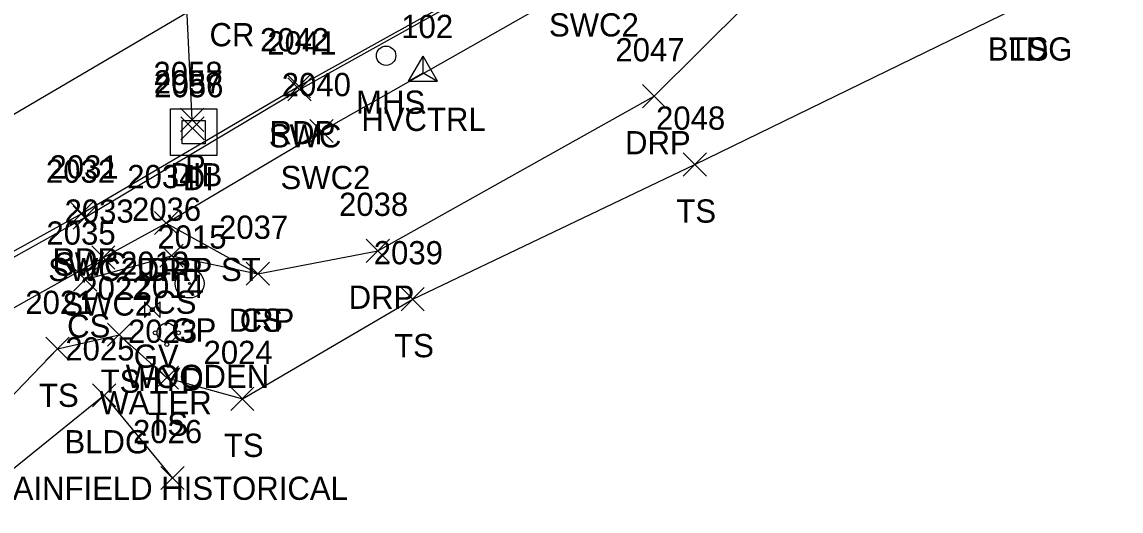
# Model space of a CAD drawing. Extents: x 1657482 to 1661439, y 647981 to 649041.
# Drawn here: x 1660079.4 to 1660173.9, y 648150.8 to 648192.9 of the extents above; entities that cross this region are included whole.
import ezdxf

# ---------------------------------------------------------------- set-up
doc = ezdxf.new("R2010")
doc.units = 0
for name, color, linetype in [('C_A', 7, 'Continuous'), ('C_I', 7, 'Continuous'), ('CPSM', 7, 'Continuous'), ('D_A', 7, 'Continuous'), ('D_I', 7, 'Continuous'), ('D_TIC', 7, 'Continuous'), ('DCP', 7, 'Continuous'), ('DS', 7, 'Continuous'), ('L_A', 7, 'Continuous'), ('L_C', 7, 'Continuous'), ('L_I', 7, 'Continuous'), ('L_TIC', 7, 'Continuous'), ('LBC', 7, 'Continuous'), ('LELB', 7, 'Continuous'), ('P_A', 7, 'Continuous'), ('P_I', 7, 'Continuous'), ('P_TIC', 7, 'Continuous'), ('PET', 7, 'Continuous'), ('PRC', 7, 'Continuous'), ('R_A', 7, 'Continuous'), ('R_C', 7, 'Continuous'), ('R_I', 7, 'Continuous'), ('R_TIC', 7, 'Continuous'), ('RDP', 7, 'Continuous'), ('RGP', 7, 'Continuous'), ('RSW', 7, 'Continuous'), ('U_A', 7, 'Continuous'), ('U_C', 7, 'Continuous'), ('U_I', 7, 'Continuous'), ('USMH', 7, 'Continuous'), ('UWFH', 7, 'Continuous'), ('UWV', 7, 'Continuous')]:
    doc.layers.add(name, color=color, linetype=linetype)

msp = doc.modelspace()

# ---------------------------------------------------------------- linework, layer by layer
at = {"layer": 'CPSM'}
for p, q in [((1660112.623, 648187.758), (1660113.873, 648189.923)), ((1660115.123, 648187.758), (1660113.873, 648189.923)), ((1660113.873, 648188.479), (1660113.873, 648189.923)), ((1660112.623, 648187.758), (1660113.873, 648188.479)), ((1660113.873, 648188.479), (1660113.873, 648188.479)), ((1660113.873, 648188.479), (1660115.123, 648187.758)), ((1660112.623, 648187.758), (1660115.123, 648187.758))]:
    msp.add_line(p, q, dxfattribs=at)
at = {"layer": 'D_TIC'}
for points in [[(1660093.024, 648183.435), (1660095.024, 648185.435)], [(1660095.024, 648183.435), (1660093.024, 648185.435)], [(1660093.048, 648182.707), (1660095.048, 648184.707)], [(1660095.048, 648182.707), (1660093.048, 648184.707)]]:
    msp.add_lwpolyline(points, dxfattribs=at)
at = {"layer": 'DCP'}
msp.add_lwpolyline([(1660094.024, 648184.435), (1660093.004, 648205.604)], dxfattribs=at)
at = {"layer": 'DS'}
for p, q in [((1660092.146, 648185.375), (1660096.146, 648185.375)), ((1660092.146, 648181.375), (1660092.146, 648185.375)), ((1660096.146, 648185.375), (1660096.146, 648181.375)), ((1660093.146, 648182.375), (1660093.146, 648184.375)), ((1660093.146, 648184.375), (1660095.146, 648184.375)), ((1660095.146, 648184.375), (1660095.146, 648182.375)), ((1660094.151, 648183.377), (1660094.151, 648183.377)), ((1660094.151, 648183.377), (1660094.151, 648183.377)), ((1660095.146, 648182.375), (1660093.146, 648182.375)), ((1660096.146, 648181.375), (1660092.146, 648181.375))]:
    msp.add_line(p, q, dxfattribs=at)
at = {"layer": 'L_TIC'}
for points in [[(1660136.252, 648179.586), (1660138.252, 648181.586)], [(1660138.252, 648179.586), (1660136.252, 648181.586)], [(1660091.233, 648171.74), (1660093.233, 648173.74)], [(1660093.233, 648171.74), (1660091.233, 648173.74)], [(1660098.665, 648170.191), (1660100.665, 648172.191)], [(1660100.665, 648170.191), (1660098.665, 648172.191)], [(1660083.823, 648169.69), (1660085.823, 648171.69)], [(1660085.823, 648169.69), (1660083.823, 648171.69)], [(1660111.982, 648167.997), (1660113.982, 648169.997)], [(1660113.982, 648167.997), (1660111.982, 648169.997)], [(1660086.736, 648164.939), (1660088.736, 648166.939)], [(1660088.736, 648164.939), (1660086.736, 648166.939)], [(1660081.438, 648163.723), (1660083.438, 648165.723)], [(1660083.438, 648163.723), (1660081.438, 648165.723)], [(1660090.837, 648161.237), (1660092.837, 648163.237)], [(1660092.837, 648161.237), (1660090.837, 648163.237)], [(1660085.444, 648159.719), (1660087.444, 648161.719)], [(1660087.444, 648159.719), (1660085.444, 648161.719)], [(1660097.334, 648159.413), (1660099.334, 648161.413)], [(1660099.334, 648159.413), (1660097.334, 648161.413)], [(1660091.319, 648152.599), (1660093.319, 648154.599)], [(1660093.319, 648152.599), (1660091.319, 648154.599)]]:
    msp.add_lwpolyline(points, dxfattribs=at)
at = {"layer": 'LBC'}
msp.add_lwpolyline([(1660067.676, 648144.921), (1660075.653, 648152.015), (1660086.444, 648160.719), (1660092.319, 648153.599)], dxfattribs=at)
at = {"layer": 'LELB'}
for points in [[(1660062.987, 648150.882), (1660075.31, 648157.317), (1660082.438, 648164.723), (1660087.736, 648165.939), (1660091.837, 648162.237), (1660098.334, 648160.413), (1660112.982, 648168.997), (1660137.252, 648180.586), (1660165.85, 648194.537)], [(1660084.823, 648170.69), (1660092.233, 648172.74), (1660099.665, 648171.191)]]:
    msp.add_lwpolyline(points, dxfattribs=at)
at = {"layer": 'P_TIC'}
for points in [[(1660102.189, 648186.334), (1660104.189, 648188.334)], [(1660104.189, 648186.334), (1660102.189, 648188.334)], [(1660083.515, 648175.384), (1660085.515, 648177.384)], [(1660085.515, 648175.384), (1660083.515, 648177.384)]]:
    msp.add_lwpolyline(points, dxfattribs=at)
at = {"layer": 'PET'}
msp.add_lwpolyline([(1660002.916, 648130.398), (1660023.122, 648141.511), (1660054.019, 648158.569), (1660066.127, 648166.199), (1660084.515, 648176.384), (1660103.189, 648187.334), (1660126.126, 648200.097), (1660157.801, 648218.155), (1660193.819, 648238.551)], dxfattribs=at)
at = {"layer": 'PRC'}
msp.add_lwpolyline([(1659666.144, 648110.534), (1659699.551, 648107.376), (1659729.526, 648104.331), (1659765.503, 648101.141), (1659792.988, 648098.376), (1659818.732, 648097.206), (1659849.225, 648095.841), (1659870.331, 648096.361), (1659894.597, 648099.456), (1659913.112, 648103.656), (1659935.294, 648110.794), (1659956.941, 648119.929), (1659978.865, 648130.6), (1660002.085, 648142.328), (1660031.609, 648158.263), (1660061.231, 648174.691), (1660097.076, 648195.768), (1660113.884, 648205.485), (1660151.727, 648227.302), (1660188.688, 648248.658)], dxfattribs=at)
at = {"layer": 'R_TIC'}
for points in [[(1660102.25, 648186.06), (1660104.25, 648188.06)], [(1660104.25, 648186.06), (1660102.25, 648188.06)], [(1660132.757, 648185.469), (1660134.757, 648187.469)], [(1660134.757, 648185.469), (1660132.757, 648187.469)], [(1660104.145, 648182.473), (1660106.145, 648184.473)], [(1660106.145, 648182.473), (1660104.145, 648184.473)], [(1660083.779, 648175.019), (1660085.779, 648177.019)], [(1660085.779, 648175.019), (1660083.779, 648177.019)], [(1660090.773, 648174.551), (1660092.773, 648176.551)], [(1660092.773, 648174.551), (1660090.773, 648176.551)], [(1660090.773, 648174.551), (1660092.773, 648176.551)], [(1660092.773, 648174.551), (1660090.773, 648176.551)], [(1660108.987, 648172.164), (1660110.987, 648174.164)], [(1660110.987, 648172.164), (1660108.987, 648174.164)], [(1660085.381, 648171.581), (1660087.381, 648173.581)], [(1660087.381, 648171.581), (1660085.381, 648173.581)], [(1660098.665, 648170.191), (1660100.665, 648172.191)], [(1660100.665, 648170.191), (1660098.665, 648172.191)]]:
    msp.add_lwpolyline(points, dxfattribs=at)
at = {"layer": 'RDP'}
msp.add_lwpolyline([(1660091.773, 648175.551), (1660099.665, 648171.191), (1660109.987, 648173.164), (1660133.757, 648186.469), (1660145.687, 648198.363), (1660156.807, 648212.923)], dxfattribs=at)
at = {"layer": 'RGP'}
msp.add_line((1660093.796, 648170.349), (1660093.796, 648170.349), dxfattribs=at)
for radius in [1.25, 0.0833]:
    msp.add_circle((1660093.796, 648170.349), radius, dxfattribs=at)
at = {"layer": 'RSW'}
for points in [[(1660054.019, 648158.569), (1660066.26, 648165.695), (1660084.779, 648176.019), (1660103.25, 648187.06), (1660126.268, 648199.916), (1660157.801, 648218.155)], [(1660058.192, 648152.49), (1660068.162, 648162.382), (1660086.381, 648172.581), (1660091.773, 648175.551), (1660105.145, 648183.473), (1660128.233, 648196.611), (1660156.807, 648212.923), (1660160.174, 648214.588)]]:
    msp.add_lwpolyline(points, dxfattribs=at)
at = {"layer": 'USMH'}
for p, q in [((1660110.696, 648189.958), (1660110.696, 648189.958)), ((1660111.529, 648189.958), (1660111.529, 648189.958))]:
    msp.add_line(p, q, dxfattribs=at)
msp.add_circle((1660110.696, 648189.958), 0.833, dxfattribs=at)
at = {"layer": 'UWFH'}
msp.add_line((1660091.837, 648166.101), (1660091.837, 648166.101), dxfattribs=at)
for centre, radius in [((1660090.837, 648166.101), 0.167), ((1660091.837, 648166.101), 0.833), ((1660092.837, 648166.101), 0.167), ((1660091.837, 648165.101), 0.167)]:
    msp.add_circle(centre, radius, dxfattribs=at)
at = {"layer": 'UWV'}
for p, q in [((1660089.92, 648168.761), (1660091.253, 648167.427)), ((1660091.253, 648168.761), (1660089.92, 648167.427))]:
    msp.add_line(p, q, dxfattribs=at)
for points in [[(1660089.92, 648168.761), (1660089.92, 648167.427)], [(1660091.253, 648167.427), (1660091.253, 648168.761)]]:
    msp.add_lwpolyline(points, dxfattribs=at)
msp.add_circle((1660090.587, 648168.094), 0.167, dxfattribs=at)

# ---------------------------------------------------------------- texts
at = {"layer": 'C_A'}
msp.add_text('HVCTRL', height=2, dxfattribs=at).set_placement((1660108.566, 648183.479))
at = {"layer": 'C_I'}
msp.add_text('102', height=2, dxfattribs=at).set_placement((1660111.999, 648191.479))
at = {"layer": 'D_A'}
for s, p in [('P', (1660093.402, 648179.435)), ('DIB', (1660092.15, 648178.707)), ('DI', (1660093.206, 648178.377))]:
    msp.add_text(s, height=2, dxfattribs=at).set_placement(p)
at = {"layer": 'D_I'}
for s, p in [('2058', (1660090.686, 648187.435)), ('2057', (1660090.709, 648186.707)), ('2056', (1660090.757, 648186.377))]:
    msp.add_text(s, height=2, dxfattribs=at).set_placement(p)
at = {"layer": 'L_A'}
for s, p in [('BLDG', (1660162.44, 648189.537)), ('TS', (1660164.259, 648189.537)), ('TS', (1660135.661, 648175.586)), ('CS', (1660090.674, 648167.74)), ('CS', (1660098.106, 648166.191)), ('CS', (1660083.264, 648165.69)), ('TS', (1660111.391, 648163.997)), ('TS', (1660086.146, 648160.939)), ('TS', (1660080.847, 648159.723)), ('TS', (1660090.246, 648157.237)), ('BLDG', (1660083.034, 648155.719)), ('TS', (1660096.744, 648155.413))]:
    msp.add_text(s, height=2, dxfattribs=at).set_placement(p)
at = {"layer": 'L_C'}
msp.add_text('1 STORY PLAINFIELD HISTORICAL', height=2, dxfattribs=at).set_placement((1660063.122, 648151.719))
at = {"layer": 'L_I'}
for s, p in [('2048', (1660133.913, 648183.586)), ('2036', (1660088.839, 648175.74)), ('2035', (1660081.484, 648173.69)), ('2037', (1660096.326, 648174.191)), ('2039', (1660109.635, 648171.997)), ('2022', (1660084.398, 648168.939)), ('2021', (1660079.666, 648167.723)), ('2023', (1660088.498, 648165.237)), ('2025', (1660083.105, 648163.719)), ('2024', (1660094.996, 648163.413)), ('2026', (1660088.925, 648156.599))]:
    msp.add_text(s, height=2, dxfattribs=at).set_placement(p)
at = {"layer": 'P_A'}
for s, p in [('CR', (1660095.509, 648190.768)), ('RDP', (1660100.677, 648182.334)), ('RDP', (1660082.004, 648171.384))]:
    msp.add_text(s, height=2, dxfattribs=at).set_placement(p)
at = {"layer": 'P_I'}
for s, p in [('2042', (1660099.851, 648190.334)), ('2031', (1660081.744, 648179.384))]:
    msp.add_text(s, height=2, dxfattribs=at).set_placement(p)
at = {"layer": 'R_A'}
for s, p in [('SWC2', (1660124.706, 648191.611)), ('SWC', (1660100.612, 648182.06)), ('DRP', (1660131.246, 648181.469)), ('SWC2', (1660101.618, 648178.473)), ('SWC', (1660082.141, 648171.019)), ('SWC2 DRP ST', (1660081.639, 648170.551)), ('DRP', (1660089.261, 648170.551)), ('DRP', (1660107.476, 648168.164)), ('SWC2', (1660082.854, 648167.581)), ('DRP', (1660097.153, 648166.191)), ('GP', (1660092.229, 648165.349))]:
    msp.add_text(s, height=2, dxfattribs=at).set_placement(p)
at = {"layer": 'R_C'}
msp.add_text('WOODEN', height=2, dxfattribs=at).set_placement((1660088.308, 648161.349))
at = {"layer": 'R_I'}
for s, p in [('2041', (1660100.479, 648190.06)), ('2047', (1660130.419, 648189.469)), ('2040', (1660101.72, 648186.473)), ('2032', (1660081.441, 648179.019)), ('2034', (1660088.435, 648178.551)), ('2034', (1660088.435, 648178.551)), ('2033', (1660083.043, 648175.581)), ('2038', (1660106.649, 648176.164)), ('2037', (1660096.326, 648174.191)), ('2015', (1660091.024, 648173.349))]:
    msp.add_text(s, height=2, dxfattribs=at).set_placement(p)
at = {"layer": 'U_A'}
for s, p in [('MHS', (1660108.113, 648184.958)), ('GV', (1660088.988, 648163.094)), ('HYD', (1660089.356, 648161.101))]:
    msp.add_text(s, height=2, dxfattribs=at).set_placement(p)
at = {"layer": 'U_C'}
msp.add_text('WATER', height=2, dxfattribs=at).set_placement((1660086.043, 648159.094))
at = {"layer": 'U_I'}
for s, p in [('2013', (1660087.815, 648171.094)), ('2014', (1660089.065, 648169.101))]:
    msp.add_text(s, height=2, dxfattribs=at).set_placement(p)

doc.saveas('drawing.dxf')
